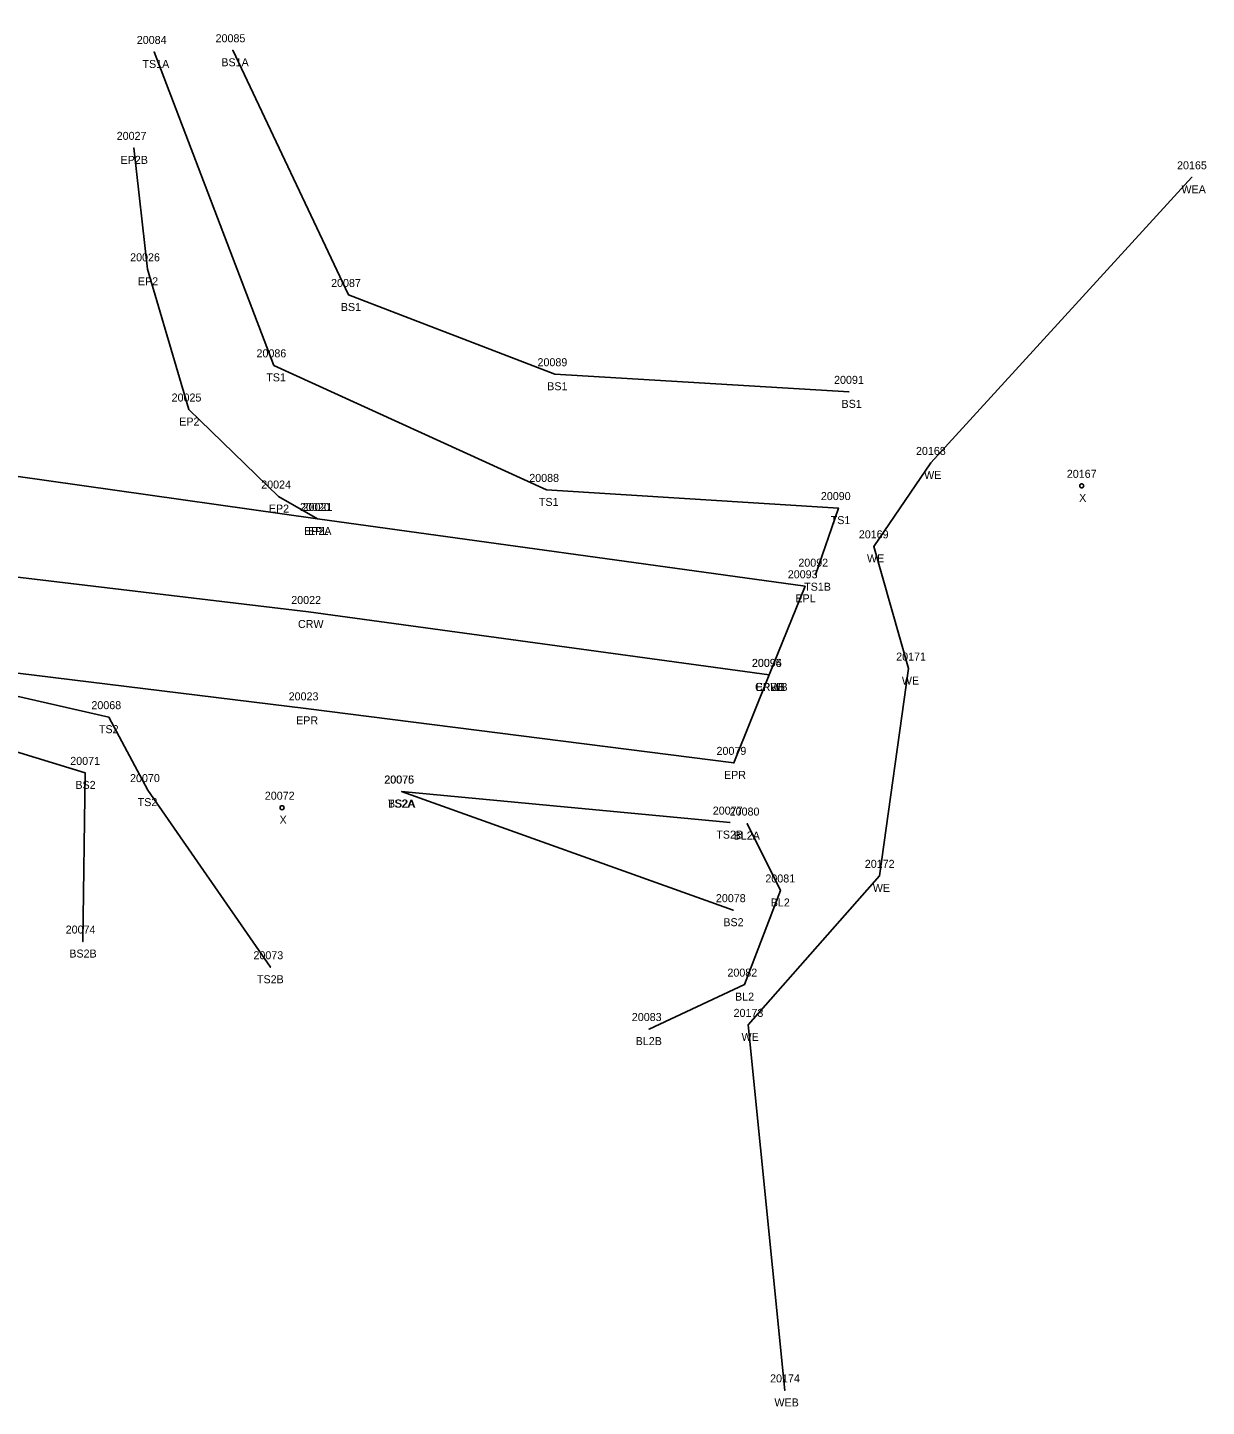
# Model space of a CAD drawing. Extents: x 2080935 to 2082049, y 730754 to 730962.
# Drawn here: x 2081377.1 to 2081524.3, y 730775.1 to 730947.4 of the extents above; entities that cross this region are included whole.
import ezdxf

# ---------------------------------------------------------------- set-up
doc = ezdxf.new("R2010")
doc.units = 0
for name, color, linetype in [('RD_DTM_BkLn1', 7, 'Continuous'), ('RD_DTM_BkLn2', 7, 'Continuous'), ('RD_EX_H2O', 7, 'Continuous'), ('RD_EX_H2O_txCode', 7, 'Continuous'), ('RD_EX_Road', 7, 'Continuous'), ('RD_EX_Road_txCode', 7, 'Continuous'), ('RD_Sketch8', 7, 'Continuous'), ('RD_SMD_Locator', 7, 'Continuous'), ('RD_SMD_Misc', 7, 'Continuous')]:
    doc.layers.add(name, color=color, linetype=linetype)

msp = doc.modelspace()

# ---------------------------------------------------------------- linework, layer by layer
at = {"layer": 'RD_DTM_BkLn1'}
for points in [[(2080941.25, 730935.08), (2081045.42, 730921.9), (2081147.52, 730908.57), (2081249.67, 730895.22), (2081352.74, 730881.46), (2081412.15, 730874.37), (2081469.7, 730866.51)], [(2081466.95, 730847.94), (2081471.09, 730839.58), (2081466.62, 730827.82), (2081454.68, 730822.27)]]:
    msp.add_lwpolyline(points, dxfattribs=at)
at = {"layer": 'RD_DTM_BkLn2'}
msp.add_line((2081423.78, 730851.94), (2081464.8, 730848.06), dxfattribs=at)
for points in [[(2081392.86, 730944.33), (2081407.83, 730905.18), (2081441.88, 730889.62), (2081478.34, 730887.35), (2081475.49, 730879.03)], [(2081402.69, 730944.54), (2081417.13, 730913.97), (2081442.9, 730904.07), (2081479.67, 730901.87)], [(2080937.44, 730917.14), (2081043.42, 730899.5), (2081145.18, 730884.99), (2081213.57, 730879.31), (2081219.84, 730884.63), (2081248.03, 730882.14), (2081293.17, 730875.78), (2081295.97, 730870.07), (2081341.8, 730864.37), (2081343.7, 730868.33), (2081350.17, 730868.41), (2081364.36, 730860.34), (2081384.26, 730854.27), (2081383.97, 730833.2)], [(2081357.97, 730867.88), (2081387.21, 730861.23), (2081392.06, 730852.12), (2081407.42, 730829.99)], [(2081423.78, 730851.94), (2081465.19, 730837.12)]]:
    msp.add_lwpolyline(points, dxfattribs=at)
at = {"layer": 'RD_EX_H2O'}
msp.add_lwpolyline([(2081522.49, 730928.67), (2081489.88, 730892.99), (2081482.74, 730882.57), (2081487.1, 730867.3), (2081483.47, 730841.41), (2081467.07, 730822.79), (2081471.63, 730777.13)], dxfattribs=at)
at = {"layer": 'RD_EX_Road'}
for points in [[(2080942.12, 730947.38), (2081047.3, 730933.82), (2081149.12, 730920.41), (2081250.8, 730907.26), (2081354.36, 730894.35), (2081413.29, 730885.99), (2081474.17, 730877.58), (2081469.7, 730866.51)], [(2081413.29, 730885.99), (2081408.4, 730888.79), (2081397.21, 730899.66), (2081392.05, 730917.18), (2081390.34, 730932.35)], [(2080939.88, 730923.83), (2081043.62, 730910.24), (2081146.95, 730896.77), (2081220.01, 730886.78), (2081221.02, 730889.92), (2081249.39, 730886.24), (2081293.86, 730880.24), (2081293.66, 730877.5), (2081351.01, 730869.76), (2081411.83, 730862.33), (2081465.27, 730855.52), (2081469.7, 730866.51)]]:
    msp.add_lwpolyline(points, dxfattribs=at)
at = {"layer": 'RD_SMD_Locator'}
for centre, radius in [((2081392.86, 730944.33), 0.001), ((2081402.69, 730944.54), 0.001), ((2081390.34, 730932.35), 0.001), ((2081522.49, 730928.67), 0.001), ((2081392.05, 730917.18), 0.001), ((2081417.13, 730913.97), 0.001), ((2081407.83, 730905.18), 0.001), ((2081442.9, 730904.07), 0.001), ((2081479.67, 730901.87), 0.001), ((2081397.21, 730899.66), 0.001), ((2081489.88, 730892.99), 0.001), ((2081508.72, 730890.13), 0.25), ((2081408.4, 730888.79), 0.001), ((2081441.88, 730889.62), 0.001), ((2081478.34, 730887.35), 0.001), ((2081413.29, 730885.99), 0.001), ((2081413.29, 730885.99), 0.001), ((2081482.74, 730882.57), 0.001), ((2081475.49, 730879.03), 0.001), ((2081474.17, 730877.58), 0.001), ((2081412.15, 730874.37), 0.001), ((2081469.7, 730866.51), 0.001), ((2081469.7, 730866.51), 0.001), ((2081469.7, 730866.51), 0.001), ((2081487.1, 730867.3), 0.001), ((2081411.83, 730862.33), 0.001), ((2081387.21, 730861.23), 0.001), ((2081465.27, 730855.52), 0.001), ((2081384.26, 730854.27), 0.001), ((2081392.06, 730852.12), 0.001), ((2081423.78, 730851.94), 0.001), ((2081423.78, 730851.94), 0.001), ((2081408.84, 730849.92), 0.25), ((2081464.8, 730848.06), 0.001), ((2081466.95, 730847.94), 0.001), ((2081483.47, 730841.41), 0.001), ((2081471.09, 730839.58), 0.001), ((2081465.19, 730837.12), 0.001), ((2081383.97, 730833.2), 0.001), ((2081407.42, 730829.99), 0.001), ((2081466.62, 730827.82), 0.001), ((2081467.07, 730822.79), 0.001), ((2081454.68, 730822.27), 0.001), ((2081471.63, 730777.13), 0.001)]:
    msp.add_circle(centre, radius, dxfattribs=at)

# ---------------------------------------------------------------- texts
at = {"layer": 'RD_EX_H2O_txCode'}
for s, p in [('20165', (2081520.63, 730929.67)), ('WEA', (2081521.18, 730926.67)), ('20168', (2081488.02, 730893.99)), ('WE', (2081489.04, 730890.99)), ('20169', (2081480.88, 730883.57)), ('WE', (2081481.9, 730880.57)), ('20171', (2081485.55, 730868.3)), ('WE', (2081486.26, 730865.3)), ('20172', (2081481.63, 730842.41)), ('WE', (2081482.63, 730839.41)), ('20173', (2081465.24, 730823.79)), ('WE', (2081466.23, 730820.79)), ('20174', (2081469.8, 730778.13)), ('WEB', (2081470.34, 730775.13))]:
    msp.add_text(s, height=1, dxfattribs=at).set_placement(p)
at = {"layer": 'RD_EX_Road_txCode'}
for s, p in [('20027', (2081388.19, 730933.35)), ('EP2B', (2081388.67, 730930.35)), ('20026', (2081389.87, 730918.18)), ('EP2', (2081390.84, 730915.18)), ('20025', (2081395.05, 730900.66)), ('EP2', (2081396, 730897.66)), ('20024', (2081406.24, 730889.79)), ('20020', (2081411.09, 730886.99)), ('20021', (2081411.41, 730886.99)), ('EP2', (2081407.19, 730886.79)), ('EP2A', (2081411.59, 730883.99)), ('EPL', (2081412.08, 730883.99)), ('20093', (2081472.01, 730878.58)), ('EPL', (2081472.96, 730875.58)), ('20096', (2081467.52, 730867.51)), ('20095', (2081467.54, 730867.51)), ('20023', (2081409.67, 730863.33)), ('EPRB', (2081468, 730864.51)), ('EPLB', (2081468.03, 730864.51)), ('EPR', (2081410.6, 730860.33)), ('20079', (2081463.11, 730856.52)), ('EPR', (2081464.04, 730853.52))]:
    msp.add_text(s, height=1, dxfattribs=at).set_placement(p)
at = {"layer": 'RD_Sketch8'}
for s, p in [('20167', (2081506.86, 730891.13)), ('X', (2081508.4, 730888.13)), ('20072', (2081406.69, 730850.92)), ('X', (2081408.53, 730847.92))]:
    msp.add_text(s, height=1, dxfattribs=at).set_placement(p)
at = {"layer": 'RD_SMD_Misc'}
for s, p in [('20085', (2081400.54, 730945.54)), ('20084', (2081390.7, 730945.33)), ('TS1A', (2081391.41, 730942.33)), ('BS1A', (2081401.26, 730942.54)), ('20087', (2081414.97, 730914.97)), ('BS1', (2081416.18, 730911.97)), ('20086', (2081405.65, 730906.18)), ('20089', (2081440.75, 730905.07)), ('TS1', (2081406.87, 730903.18)), ('20091', (2081477.79, 730902.87)), ('BS1', (2081441.96, 730902.07)), ('BS1', (2081478.72, 730899.87)), ('20088', (2081439.72, 730890.62)), ('TS1', (2081440.92, 730887.62)), ('20090', (2081476.14, 730888.35)), ('TS1', (2081477.37, 730885.35)), ('20092', (2081473.33, 730880.03)), ('TS1B', (2081474.05, 730877.03)), ('20022', (2081409.99, 730875.37)), ('CRW', (2081410.83, 730872.37)), ('20094', (2081467.54, 730867.51)), ('CRWB', (2081467.91, 730864.51)), ('20068', (2081385.03, 730862.23)), ('TS2', (2081385.97, 730859.23)), ('20071', (2081382.39, 730855.27)), ('20070', (2081389.86, 730853.12)), ('20076', (2081421.6, 730852.94)), ('20075', (2081421.63, 730852.94)), ('BS2', (2081383.03, 730852.27)), ('TS2', (2081390.81, 730850.12)), ('TS2A', (2081422.05, 730849.94)), ('BS2A', (2081422.07, 730849.94)), ('20077', (2081462.64, 730849.06)), ('20080', (2081464.75, 730848.94)), ('TS2B', (2081463.08, 730846.06)), ('BL2A', (2081465.25, 730845.94)), ('20081', (2081469.21, 730840.58)), ('20078', (2081463.03, 730838.12)), ('BL2', (2081469.88, 730837.58)), ('20074', (2081381.82, 730834.2)), ('BS2', (2081463.96, 730835.12)), ('BS2B', (2081382.27, 730831.2)), ('20073', (2081405.27, 730830.99)), ('20082', (2081464.47, 730828.82)), ('TS2B', (2081405.71, 730827.99)), ('BL2', (2081465.42, 730825.82)), ('20083', (2081452.53, 730823.27)), ('BL2B', (2081453.01, 730820.27))]:
    msp.add_text(s, height=1, dxfattribs=at).set_placement(p)

doc.saveas('drawing.dxf')
